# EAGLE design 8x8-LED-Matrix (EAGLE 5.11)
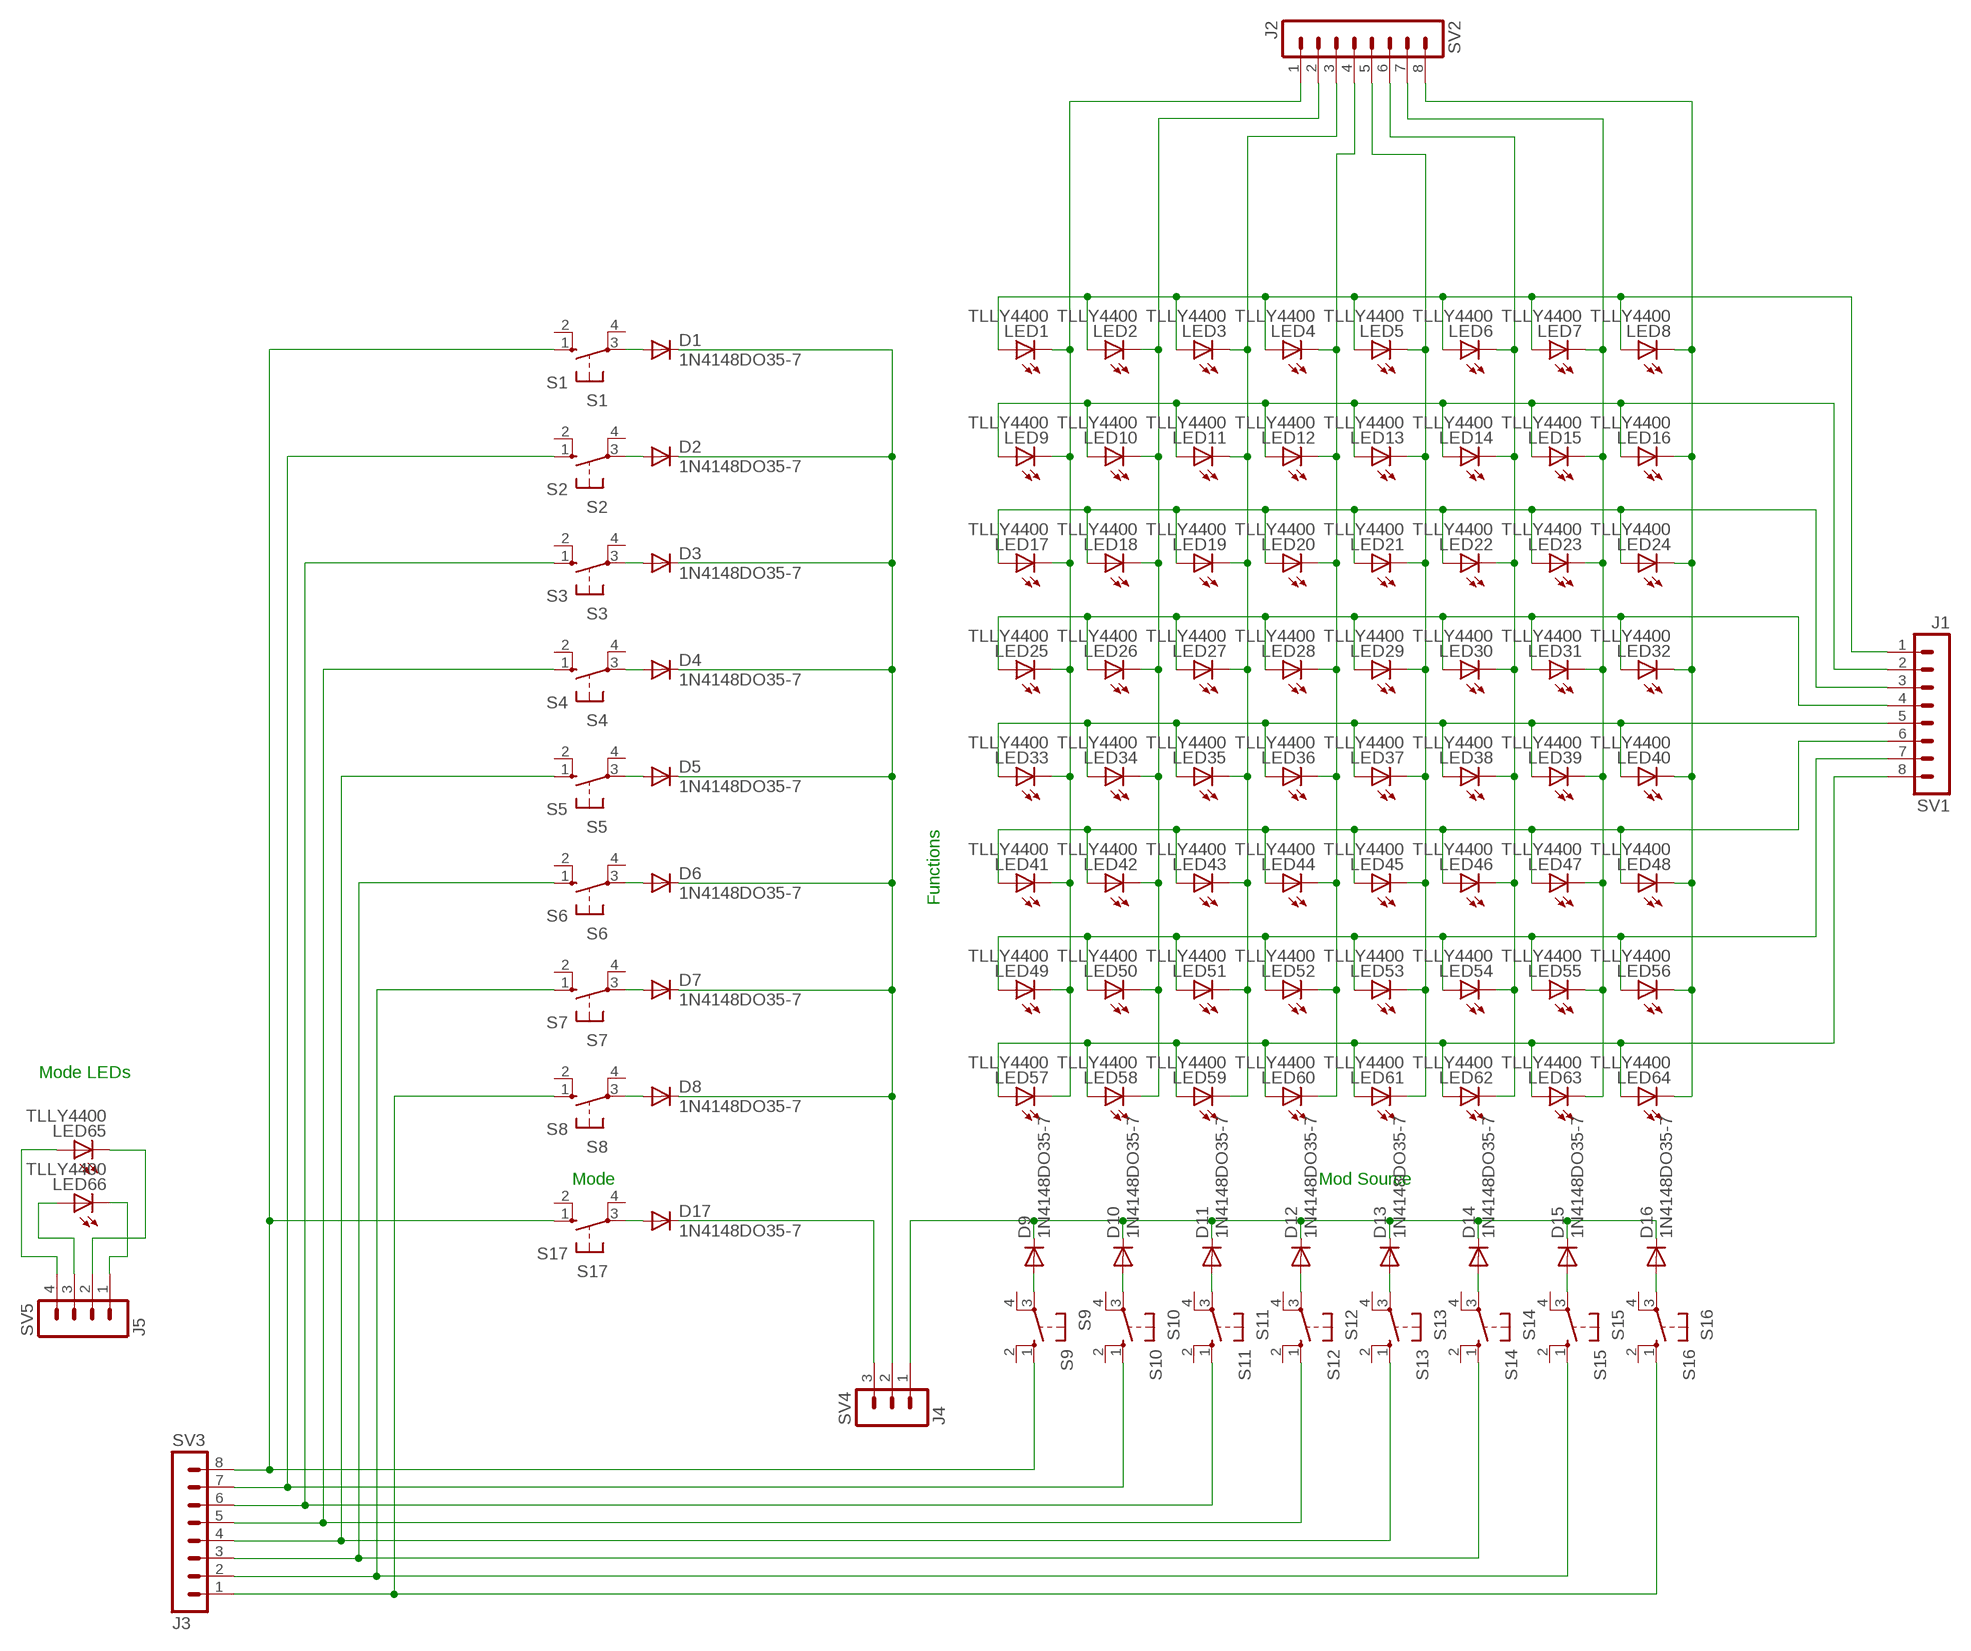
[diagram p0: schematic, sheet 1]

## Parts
D1  1N4148DO35-7  [DO35-7]
D2  1N4148DO35-7  [DO35-7]
D3  1N4148DO35-7  [DO35-7]
D4  1N4148DO35-7  [DO35-7]
D5  1N4148DO35-7  [DO35-7]
D6  1N4148DO35-7  [DO35-7]
D7  1N4148DO35-7  [DO35-7]
D8  1N4148DO35-7  [DO35-7]
D9  1N4148DO35-7  [DO35-7]
D10  1N4148DO35-7  [DO35-7]
D11  1N4148DO35-7  [DO35-7]
D12  1N4148DO35-7  [DO35-7]
D13  1N4148DO35-7  [DO35-7]
D14  1N4148DO35-7  [DO35-7]
D15  1N4148DO35-7  [DO35-7]
D16  1N4148DO35-7  [DO35-7]
D17  1N4148DO35-7  [DO35-7]
LED1  TLLY4400  [LED3MM]
LED2  TLLY4400  [LED3MM]
LED3  TLLY4400  [LED3MM]
LED4  TLLY4400  [LED3MM]
LED5  TLLY4400  [LED3MM]
LED6  TLLY4400  [LED3MM]
LED7  TLLY4400  [LED3MM]
LED8  TLLY4400  [LED3MM]
LED9  TLLY4400  [LED3MM]
LED10  TLLY4400  [LED3MM]
LED11  TLLY4400  [LED3MM]
LED12  TLLY4400  [LED3MM]
LED13  TLLY4400  [LED3MM]
LED14  TLLY4400  [LED3MM]
LED15  TLLY4400  [LED3MM]
LED16  TLLY4400  [LED3MM]
LED17  TLLY4400  [LED3MM]
LED18  TLLY4400  [LED3MM]
LED19  TLLY4400  [LED3MM]
LED20  TLLY4400  [LED3MM]
LED21  TLLY4400  [LED3MM]
LED22  TLLY4400  [LED3MM]
LED23  TLLY4400  [LED3MM]
LED24  TLLY4400  [LED3MM]
LED25  TLLY4400  [LED3MM]
LED26  TLLY4400  [LED3MM]
LED27  TLLY4400  [LED3MM]
LED28  TLLY4400  [LED3MM]
LED29  TLLY4400  [LED3MM]
LED30  TLLY4400  [LED3MM]
LED31  TLLY4400  [LED3MM]
LED32  TLLY4400  [LED3MM]
LED33  TLLY4400  [LED3MM]
LED34  TLLY4400  [LED3MM]
LED35  TLLY4400  [LED3MM]
LED36  TLLY4400  [LED3MM]
LED37  TLLY4400  [LED3MM]
LED38  TLLY4400  [LED3MM]
LED39  TLLY4400  [LED3MM]
LED40  TLLY4400  [LED3MM]
LED41  TLLY4400  [LED3MM]
LED42  TLLY4400  [LED3MM]
LED43  TLLY4400  [LED3MM]
LED44  TLLY4400  [LED3MM]
LED45  TLLY4400  [LED3MM]
LED46  TLLY4400  [LED3MM]
LED47  TLLY4400  [LED3MM]
LED48  TLLY4400  [LED3MM]
LED49  TLLY4400  [LED3MM]
LED50  TLLY4400  [LED3MM]
LED51  TLLY4400  [LED3MM]
LED52  TLLY4400  [LED3MM]
LED53  TLLY4400  [LED3MM]
LED54  TLLY4400  [LED3MM]
LED55  TLLY4400  [LED3MM]
LED56  TLLY4400  [LED3MM]
LED57  TLLY4400  [LED3MM]
LED58  TLLY4400  [LED3MM]
LED59  TLLY4400  [LED3MM]
LED60  TLLY4400  [LED3MM]
LED61  TLLY4400  [LED3MM]
LED62  TLLY4400  [LED3MM]
LED63  TLLY4400  [LED3MM]
LED64  TLLY4400  [LED3MM]
LED65  TLLY4400  [LED3MM]
LED66  TLLY4400  [LED3MM]
S1  S1  10-XX  [B3F-10XX]
S2  S2  10-XX  [B3F-10XX]
S3  S3  10-XX  [B3F-10XX]
S4  S4  10-XX  [B3F-10XX]
S5  S5  10-XX  [B3F-10XX]
S6  S6  10-XX  [B3F-10XX]
S7  S7  10-XX  [B3F-10XX]
S8  S8  10-XX  [B3F-10XX]
S9  S9  10-XX  [B3F-10XX]
S10  S10  10-XX  [B3F-10XX]
S11  S11  10-XX  [B3F-10XX]
S12  S12  10-XX  [B3F-10XX]
S13  S13  10-XX  [B3F-10XX]
S14  S14  10-XX  [B3F-10XX]
S15  S15  10-XX  [B3F-10XX]
S16  S16  10-XX  [B3F-10XX]
S17  S17  10-XX  [B3F-10XX]
SV1  J1  MA08-1  [MA08-1]
SV2  J2  MA08-1  [MA08-1]
SV3  J3  MA08-1  [MA08-1]
SV4  J4  MA03-1  [MA03-1]
SV5  J5  MA04-1  [MA04-1]

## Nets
N$1: LED1.A LED2.A LED3.A LED4.A LED5.A LED6.A LED7.A LED8.A SV1.1
N$2: LED9.A LED10.A LED11.A LED12.A LED13.A LED14.A LED15.A LED16.A SV1.2
N$3: LED17.A LED18.A LED19.A LED20.A LED21.A LED22.A LED23.A LED24.A SV1.3
N$4: LED25.A LED26.A LED27.A LED28.A LED29.A LED30.A LED31.A LED32.A SV1.4
N$5: LED33.A LED34.A LED35.A LED36.A LED37.A LED38.A LED39.A LED40.A SV1.5
N$6: LED41.A LED42.A LED43.A LED44.A LED45.A LED46.A LED47.A LED48.A SV1.6
N$7: D3.A S3.3(P)
N$8: LED57.A LED58.A LED59.A LED60.A LED61.A LED62.A LED63.A LED64.A SV1.8
N$9: LED1.K(C) LED9.K(C) LED17.K(C) LED25.K(C) LED33.K(C) LED41.K(C) LED49.K(C) LED57.K(C) SV2.1
N$10: LED2.K(C) LED10.K(C) LED18.K(C) LED26.K(C) LED34.K(C) LED42.K(C) LED50.K(C) LED58.K(C) SV2.2
N$11: LED3.K(C) LED11.K(C) LED19.K(C) LED27.K(C) LED35.K(C) LED43.K(C) LED51.K(C) LED59.K(C) SV2.3
N$12: LED4.K(C) LED12.K(C) LED20.K(C) LED28.K(C) LED36.K(C) LED44.K(C) LED52.K(C) LED60.K(C) SV2.4
N$13: LED5.K(C) LED13.K(C) LED21.K(C) LED29.K(C) LED37.K(C) LED45.K(C) LED53.K(C) LED61.K(C) SV2.5
N$14: LED6.K(C) LED14.K(C) LED22.K(C) LED30.K(C) LED38.K(C) LED46.K(C) LED54.K(C) LED62.K(C) SV2.6
N$15: LED7.K(C) LED15.K(C) LED23.K(C) LED31.K(C) LED39.K(C) LED47.K(C) LED55.K(C) LED63.K(C) SV2.7
N$16: LED8.K(C) LED16.K(C) LED24.K(C) LED32.K(C) LED40.K(C) LED48.K(C) LED56.K(C) LED64.K(C) SV2.8
N$17: LED49.A LED50.A LED51.A LED52.A LED53.A LED54.A LED55.A LED56.A SV1.7
N$18: S1.1(S) S9.1(S) S17.1(S) SV3.8
N$19: S2.1(S) S10.1(S) SV3.7
N$20: S4.1(S) S12.1(S) SV3.5
N$21: S5.1(S) S13.1(S) SV3.4
N$22: S6.1(S) S14.1(S) SV3.3
N$23: S7.1(S) S15.1(S) SV3.2
N$24: S8.1(S) S16.1(S) SV3.1
N$25: S3.1(S) S11.1(S) SV3.6
N$26: D4.A S4.3(P)
N$27: D5.A S5.3(P)
N$28: D6.A S6.3(P)
N$29: D7.A S7.3(P)
N$30: D8.A S8.3(P)
N$31: D1.C D2.C D3.C D4.C D5.C D6.C D7.C D8.C SV4.2
N$32: D9.A S9.3(P)
N$33: D10.A S10.3(P)
N$34: LED65.A SV5.4
N$35: LED66.A SV5.3
N$36: LED65.K(C) SV5.2
N$37: LED66.K(C) SV5.1
N$38: D11.A S11.3(P)
N$39: D12.A S12.3(P)
N$40: D13.A S13.3(P)
N$41: D14.A S14.3(P)
N$42: D15.A S15.3(P)
N$43: D16.A S16.3(P)
N$44: D9.C D10.C D11.C D12.C D13.C D14.C D15.C D16.C SV4.1
N$45: D17.C SV4.3
N$46: D17.A S17.3(P)
N$48: D1.A S1.3(P)
N$49: D2.A S2.3(P)
Unconnected: S1.2(S1) S1.4(P1) S2.2(S1) S2.4(P1) S3.2(S1) S3.4(P1) S4.2(S1) S4.4(P1) S5.2(S1) S5.4(P1) S6.2(S1) S6.4(P1) S7.2(S1) S7.4(P1) S8.2(S1) S8.4(P1) S9.2(S1) S9.4(P1) S10.2(S1) S10.4(P1) S11.2(S1) S11.4(P1) S12.2(S1) S12.4(P1) S13.2(S1) S13.4(P1) S14.2(S1) S14.4(P1) S15.2(S1) S15.4(P1) S16.2(S1) S16.4(P1) S17.2(S1) S17.4(P1)

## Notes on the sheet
- Functions
- Mode LEDs
- Mode | Mod Source

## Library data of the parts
D1-D17 = diode:1N4148: DIODE
LED1-LED66 = led:TLLY4400: Low Current (2mA) LED 3 mm Tinted Diffused Package color YELLOW; MF: VISHAY SEMICONDUCTOR; OC_FARNELL: 1612439
S1-S17 = switch-omron:10-XX: OMRON SWITCH; MPN: B3F-1000; OC_FARNELL: 176432; OC_NEWARK: 36M3542
SV1-SV3 = con-lstb:MA08-1: PIN HEADER; OC_FARNELL: unknown; OC_NEWARK: unknown
SV4 = con-lstb:MA03-1: PIN HEADER; OC_FARNELL: unknown; OC_NEWARK: unknown
SV5 = con-lstb:MA04-1: PIN HEADER; OC_FARNELL: unknown; OC_NEWARK: unknown

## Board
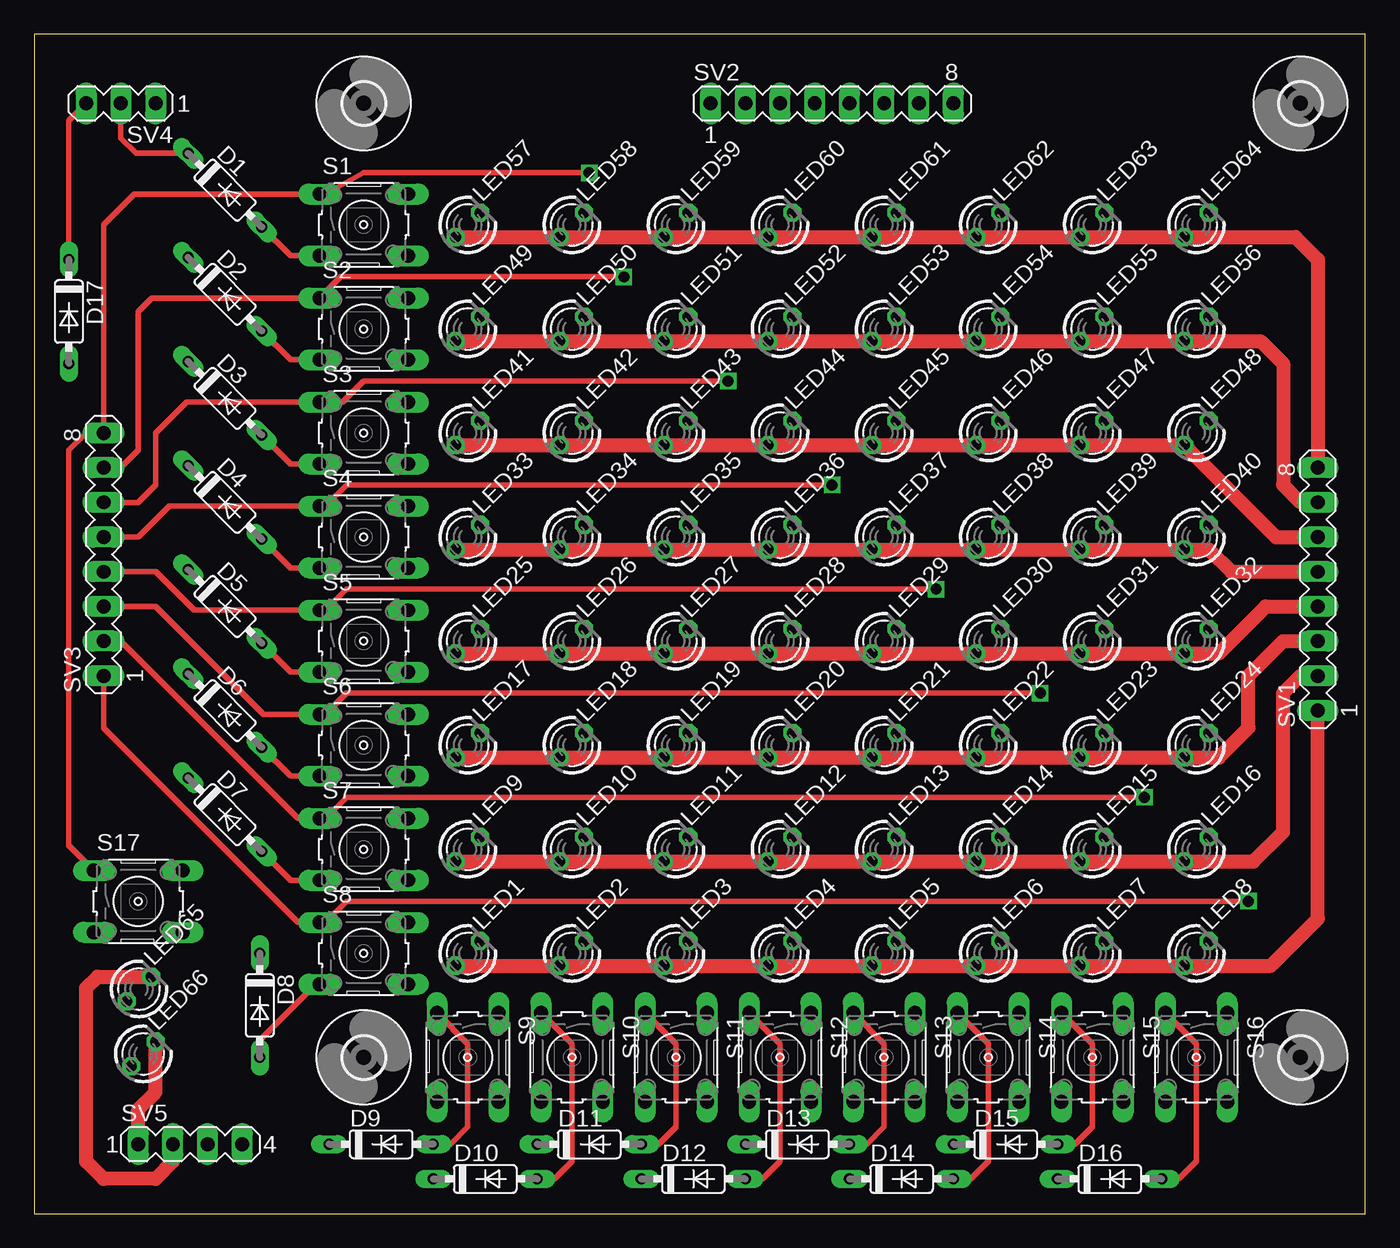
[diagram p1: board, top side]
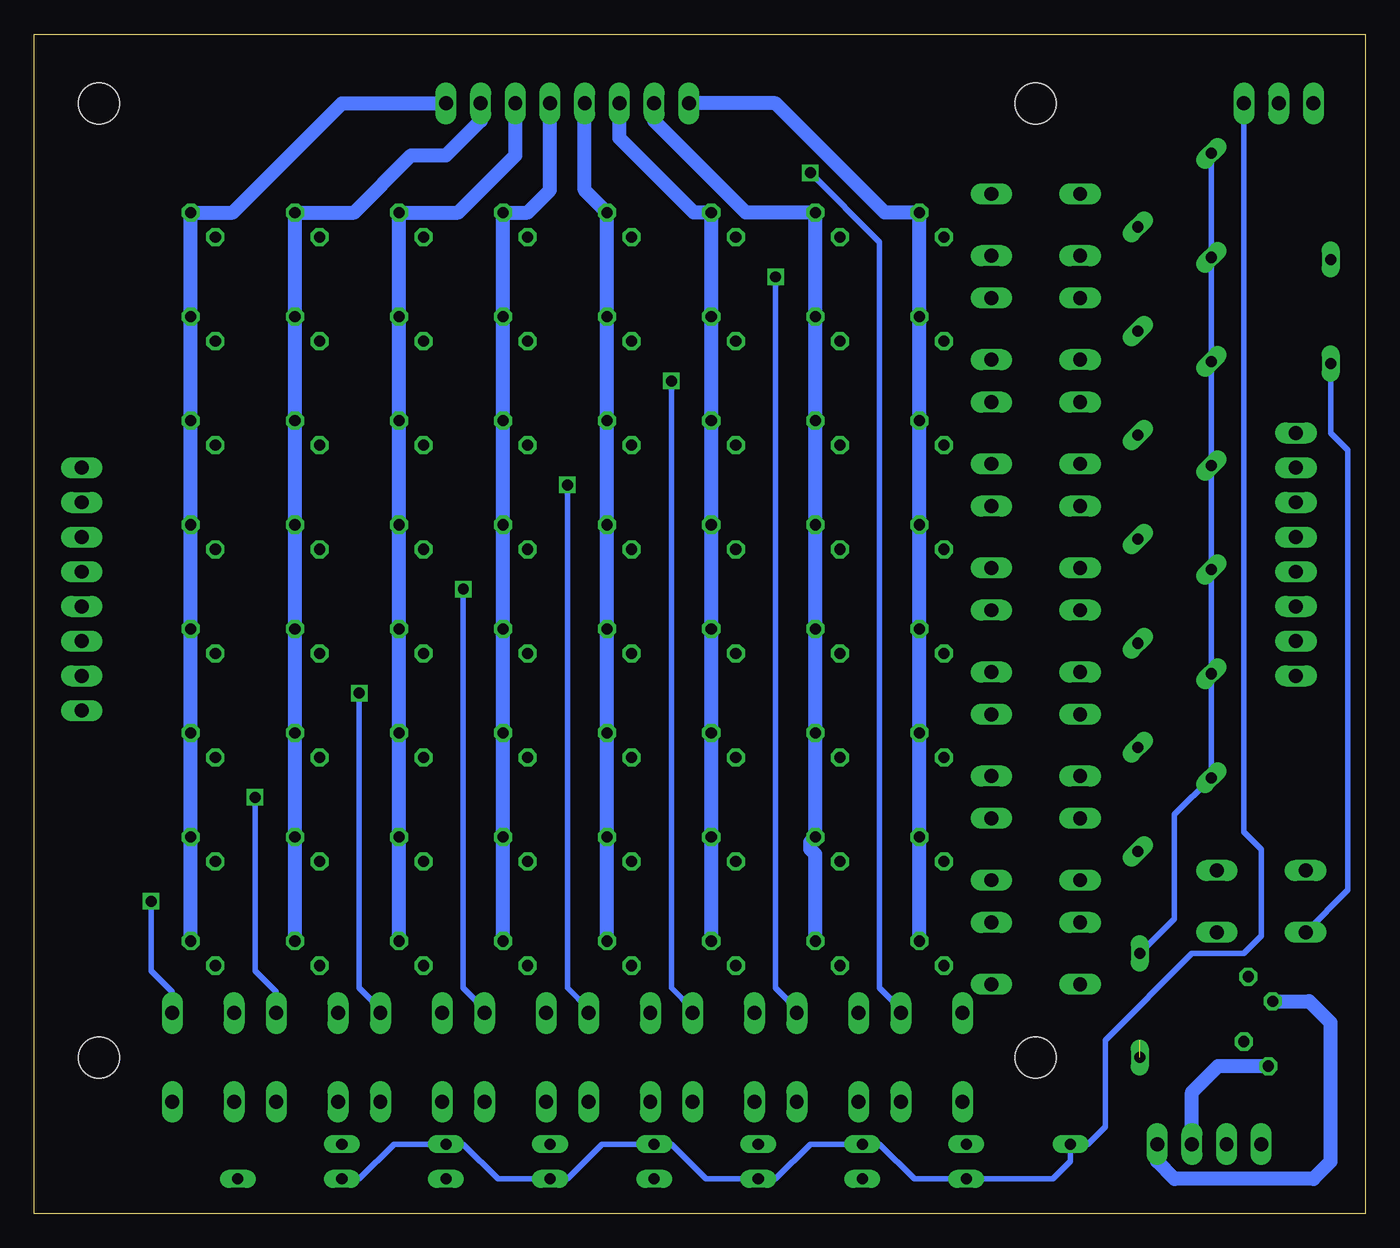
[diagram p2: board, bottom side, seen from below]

Size 97.46 x 86.35 mm. Coordinates in mm from the lower left corner, seen from the top.
Outline: 0,0 97.46,0 97.46,86.35 0,86.35 0,0
Copper layers (1*16): Top 0.035mm / dielectric 1.5mm / Bottom 0.035mm
Design rules "batchpcb": minimum track width 8mil, minimum drill 20mil, track to track 8mil, track to pad 8mil, pad to pad 8mil, via to via 8mil, smd to smd 8mil, copper to edge 40mil, drill to drill 8mil, minimum pad ring 10mil, minimum via ring 8mil, stop-mask expansion 4mil, vias tented up to drill 0mil, thermal gap 10mil

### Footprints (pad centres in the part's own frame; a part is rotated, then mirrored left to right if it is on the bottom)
DO35-7 = drill 0.813 long: A 3.81,0; C -3.81,0
LED3MM = drill 0.813 octagon: A -1.27,0; K 1.27,0
B3F-10XX = drill 1.016 long: 1 -3.251,2.261; 2 3.251,2.261; 3 -3.251,-2.261; 4 3.251,-2.261
MA08-1 = drill 1.016 long: 1 -8.89,0; 2 -6.35,0; 3 -3.81,0; 4 -1.27,0; 5 1.27,0; 6 3.81,0; 7 6.35,0; 8 8.89,0
MA03-1 = drill 1.016 long: 1 -2.54,0; 2 0,0; 3 2.54,0
MA04-1 = drill 1.016 long: 1 -3.81,0; 2 -1.27,0; 3 1.27,0; 4 3.81,0
3,0 = hole 3: 0,0

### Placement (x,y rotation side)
D1  13.97,74.93 315 top
D2  13.97,67.31 315 top
D3  13.97,59.69 315 top
D4  13.97,52.07 315 top
D5  13.97,44.45 315 top
D6  13.97,36.83 315 top
D7  13.97,29.21 315 top
D8  16.51,15.24 270 top
D9  25.4,5.08 0 top
D10  33.02,2.54 0 top
D11  40.64,5.08 0 top
D12  48.26,2.54 0 top
D13  55.88,5.08 0 top
D14  63.5,2.54 0 top
D15  71.12,5.08 0 top
D16  78.74,2.54 0 top
D17  2.54,66.04 270 top
LED1  31.75,19.05 45 top
LED2  39.37,19.05 45 top
LED3  46.99,19.05 45 top
LED4  54.61,19.05 45 top
LED5  62.23,19.05 45 top
LED6  69.85,19.05 45 top
LED7  77.47,19.05 45 top
LED8  85.09,19.05 45 top
LED9  31.75,26.67 45 top
LED10  39.37,26.67 45 top
LED11  46.99,26.67 45 top
LED12  54.61,26.67 45 top
LED13  62.23,26.67 45 top
LED14  69.85,26.67 45 top
LED15  77.47,26.67 45 top
LED16  85.09,26.67 45 top
LED17  31.75,34.29 45 top
LED18  39.37,34.29 45 top
LED19  46.99,34.29 45 top
LED20  54.61,34.29 45 top
LED21  62.23,34.29 45 top
LED22  69.85,34.29 45 top
LED23  77.47,34.29 45 top
LED24  85.09,34.29 45 top
LED25  31.75,41.91 45 top
LED26  39.37,41.91 45 top
LED27  46.99,41.91 45 top
LED28  54.61,41.91 45 top
LED29  62.23,41.91 45 top
LED30  69.85,41.91 45 top
LED31  77.47,41.91 45 top
LED32  85.09,41.91 45 top
LED33  31.75,49.53 45 top
LED34  39.37,49.53 45 top
LED35  46.99,49.53 45 top
LED36  54.61,49.53 45 top
LED37  62.23,49.53 45 top
LED38  69.85,49.53 45 top
LED39  77.47,49.53 45 top
LED40  85.09,49.53 45 top
LED41  31.75,57.15 45 top
LED42  39.37,57.15 45 top
LED43  46.99,57.15 45 top
LED44  54.61,57.15 45 top
LED45  62.23,57.15 45 top
LED46  69.85,57.15 45 top
LED47  77.47,57.15 45 top
LED48  85.09,57.15 45 top
LED49  31.75,64.77 45 top
LED50  39.37,64.77 45 top
LED51  46.99,64.77 45 top
LED52  54.61,64.77 45 top
LED53  62.23,64.77 45 top
LED54  69.85,64.77 45 top
LED55  77.47,64.77 45 top
LED56  85.09,64.77 45 top
LED57  31.75,72.39 45 top
LED58  39.37,72.39 45 top
LED59  46.99,72.39 45 top
LED60  54.61,72.39 45 top
LED61  62.23,72.39 45 top
LED62  69.85,72.39 45 top
LED63  77.47,72.39 45 top
LED64  85.09,72.39 45 top
LED65  7.68,16.45 45 top
LED66  7.99,11.69 45 top
S1  24.13,72.39 0 top
S2  24.13,64.77 0 top
S3  24.13,57.15 0 top
S4  24.13,49.53 0 top
S5  24.13,41.91 0 top
S6  24.13,34.29 0 top
S7  24.13,26.67 0 top
S8  24.13,19.05 0 top
S9  31.75,11.43 270 top
S10  39.37,11.43 270 top
S11  46.99,11.43 270 top
S12  54.61,11.43 270 top
S13  62.23,11.43 270 top
S14  69.85,11.43 270 top
S15  77.47,11.43 270 top
S16  85.09,11.43 270 top
S17  7.62,22.86 0 top
SV1  93.98,45.72 90 top
SV2  58.42,81.28 0 top
SV3  5.08,48.26 90 top
SV4  6.35,81.28 180 top
SV5  11.43,5.08 0 top
U$1  [3,0]  24.13,81.28 0 top
U$2  [3,0]  92.71,81.28 0 top
U$3  [3,0]  92.71,11.43 0 top
U$4  [3,0]  24.13,11.43 0 top

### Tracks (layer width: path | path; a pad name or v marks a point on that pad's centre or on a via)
N$1
  Top 1.016: LED1.A LED2.A LED3.A LED4.A LED5.A LED6.A LED7.A LED8.A 90.54,18.15 93.98,21.59 SV1.1
N$2
  Top 1.016: LED9.A LED10.A LED11.A LED12.A LED13.A LED14.A LED15.A LED16.A 89.27,25.77 91.44,27.94 91.44,38.1 92.71,39.37 SV1.2
N$3
  Top 1.016: LED17.A LED18.A LED19.A LED20.A LED21.A LED22.A LED23.A LED24.A 86.73,33.39 88.9,35.56 88.9,39.37 91.44,41.91 SV1.3
N$4
  Top 1.016: LED25.A LED26.A LED27.A LED28.A LED29.A LED30.A LED31.A LED32.A 86.73,41.01 90.17,44.45 SV1.4
N$5
  Top 1.016: LED33.A LED34.A LED35.A LED36.A LED37.A LED38.A LED39.A LED40.A 85.99,48.63 87.63,46.99 SV1.5
N$6
  Top 0.406: LED48.A 84.72,56.25
  Top 1.016: SV1.6 90.91,49.53 LED48.A LED47.A LED46.A LED45.A LED44.A LED43.A LED42.A LED41.A
N$7
  Top 0.406: S3.3 18.77,54.89 D3.A
N$8
  Top 1.016: LED57.A LED58.A LED59.A LED60.A LED61.A LED62.A LED63.A LED64.A 92.34,71.49 93.98,69.85 SV1.8
N$9
  Bottom 1.016: LED1.K LED9.K LED17.K LED25.K LED33.K LED41.K LED49.K LED57.K 35.19,73.29 43.18,81.28 SV2.1
N$10
  Bottom 1.016: LED2.K 40.27,26.3 40.64,26.67 40.64,27.2 LED10.K LED18.K LED26.K LED34.K LED42.K LED50.K LED58.K 45.35,73.29 52.07,80.01 SV2.2
N$11
  Bottom 1.016: LED3.K LED11.K LED19.K LED27.K LED35.K LED43.K LED51.K LED59.K 49.16,73.29 54.61,78.74 SV2.3
N$12
  Bottom 1.016: LED4.K LED12.K LED20.K LED28.K LED36.K LED44.K LED52.K LED60.K 57.15,74.93 SV2.4
N$13
  Bottom 1.016: LED5.K LED13.K LED21.K LED29.K LED37.K LED45.K LED53.K LED61.K 61.33,73.29 59.69,74.93 SV2.5
N$14
  Bottom 1.016: LED6.K LED14.K LED22.K LED30.K LED38.K LED46.K LED54.K LED62.K 66.41,73.29 62.23,77.47 SV2.6
N$15
  Bottom 1.016: LED7.K LED15.K LED23.K LED31.K LED39.K LED47.K LED55.K LED63.K 74.03,73.29 69.85,77.47 67.31,77.47 64.77,80.01 SV2.7
N$16
  Bottom 1.016: LED8.K LED16.K LED24.K LED32.K LED40.K LED48.K LED56.K LED64.K 82.92,73.29 74.93,81.28 SV2.8
N$17
  Top 1.016: LED49.A LED50.A LED51.A LED52.A LED53.A LED54.A LED55.A LED56.A 89.8,63.87 91.44,62.23 91.44,53.34 92.71,52.07 SV1.7
N$18  (via drill 0.8)
  Top 0.406: S17.1 2.54,26.95 2.54,55.88 3.81,57.15 SV3.8 5.08,72.39 7.34,74.65 S1.1 21.31,74.65 24.13,76.2 v40.64,76.2
  Bottom 0.406: S9.1 34.01,14.96 35.56,16.51 35.56,71.12 v40.64,76.2
N$19  (via drill 0.8)
  Top 0.406: v43.18,68.58 22.43,68.58 S2.1 8.61,67.03 7.62,66.04 7.62,55.88 6.35,54.61 SV3.7
  Bottom 0.406: S10.1 41.63,14.96 43.18,16.51 v43.18,68.58
N$20  (via drill 0.8)
  Top 0.406: v58.42,53.34 22.86,53.34 21.31,51.79 S4.1 9.88,51.79 7.62,49.53 SV3.5
  Bottom 0.406: S12.1 56.87,14.96 58.42,16.51 v58.42,53.34
N$21  (via drill 0.8)
  Top 0.406: v66.04,45.72 22.86,45.72 21.31,44.17 S5.1 11.71,44.17 8.89,46.99 SV3.4
  Bottom 0.406: S13.1 64.49,14.96 66.04,16.51 v66.04,45.72
N$22  (via drill 0.8)
  Top 0.406: v73.66,38.1 22.86,38.1 21.31,36.55 S6.1 16.79,36.55 8.89,44.45 SV3.3
  Bottom 0.406: S14.1 72.11,14.96 73.66,16.51 v73.66,38.1
N$23  (via drill 0.8)
  Top 0.406: v81.28,30.48 22.86,30.48 21.31,28.93 S7.1 19.33,28.93 6.35,41.91 SV3.2
  Bottom 0.406: S15.1 79.73,16.23 81.28,17.78 v81.28,30.48
N$24  (via drill 0.8)
  Top 0.406: v88.9,22.86 22.86,22.86 21.31,21.31 S8.1 19.33,21.31 5.08,35.56 SV3.1
  Bottom 0.406: S16.1 87.35,16.23 88.9,17.78 v88.9,22.86
N$25  (via drill 0.8)
  Top 0.406: v50.8,60.96 24.13,60.96 22.58,59.41 S3.1 11.15,59.41 8.89,57.15 8.89,53.34 7.62,52.07 SV3.6
  Bottom 0.406: S11.1 49.25,14.96 50.8,16.51 v50.8,60.96
N$26
  Top 0.406: S4.3 18.77,47.27 D4.A
N$27
  Top 0.406: S5.3 18.77,39.65 D5.A
N$28
  Top 0.406: S6.3 18.77,32.03 D6.A
N$29
  Top 0.406: S7.3 18.77,24.41 D7.A
N$30  (1 unrouted)
  Top 0.406: S8.3 20.6,16.79 16.51,12.7
N$31
  Top 0.406: D1.C 7.47,77.62 6.35,78.74 SV4.2
  Bottom 0.406: D8.C 13.97,21.59 13.97,29.21 D7.C D6.C D5.C D4.C D3.C D2.C D1.C
N$32
  Top 0.406: D9.A 30.48,5.08 31.75,6.35 31.75,12.42 S9.3
N$33
  Top 0.406: D10.A 38.1,2.54 39.37,3.81 39.37,12.42 S10.3
N$34
  Bottom 1.016: SV5.4 15.24,3.81 13.97,2.54 3.81,2.54 2.54,3.81 2.54,13.97 4.12,15.55 LED65.A
N$35
  Bottom 1.016: SV5.3 12.7,8.89 10.79,10.79 LED66.A
N$36
  Top 1.016: LED65.K 4.64,17.34 3.81,16.51 3.81,3.81 5.08,2.54 8.89,2.54 10.16,3.81 SV5.2
N$37
  Top 1.016: SV5.1 7.62,7.62 8.89,8.89 LED66.K | 8.89,12.7 LED66.K | LED66.K
N$38
  Top 0.406: D11.A 45.72,5.08 46.99,6.35 46.99,12.42 S11.3
N$39
  Top 0.406: D12.A 53.34,2.54 54.61,3.81 54.61,12.42 S12.3
N$40
  Top 0.406: D13.A 60.96,5.08 62.23,6.35 62.23,12.42 S13.3
N$41
  Top 0.406: D14.A 68.58,2.54 69.85,3.81 69.85,12.42 S14.3
N$42
  Top 0.406: D15.A 76.2,5.08 77.47,6.35 77.47,12.42 S15.3
N$43
  Top 0.406: D16.A 83.82,2.54 85.09,3.81 85.09,12.42 S16.3
N$44
  Bottom 0.406: D16.C 73.66,2.54 71.12,5.08 D15.C 66.04,5.08 63.5,2.54 D14.C 58.42,2.54 55.88,5.08 D13.C 50.8,5.08 48.26,2.54 D12.C 43.18,2.54 40.64,5.08 D11.C 35.56,5.08 33.02,2.54 D10.C 22.86,2.54 21.59,3.81 D9.C 20.32,5.08 19.05,6.35 19.05,12.7 12.7,19.05 8.89,19.05 7.62,20.32 7.62,26.67 8.89,27.94 SV4.1
N$45
  Top 0.406: D17.C 2.54,80.01 SV4.3
N$46
  Bottom 0.406: D17.A 2.54,57.15 1.27,55.88 1.27,23.7 S17.3
N$48
  Top 0.406: S1.3 18.77,70.13 D1.A
N$49
  Top 0.406: S2.3 18.77,62.51 D2.A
